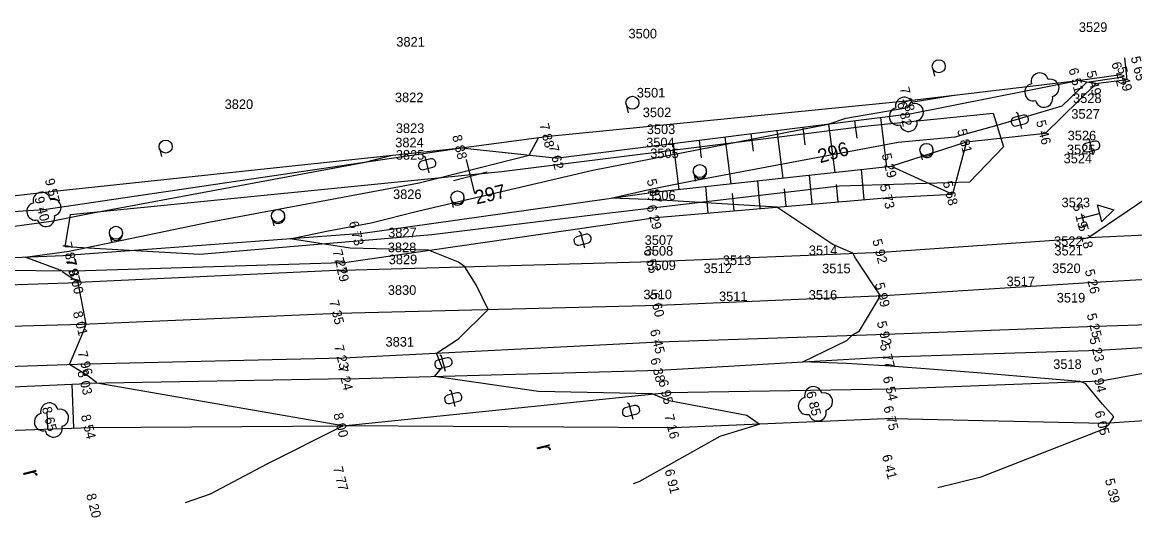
# Model space of a CAD drawing. Extents: x -740053 to -737517, y -1033516 to -1032488.
# Drawn here: x -739198.5 to -739134.6, y -1032582.4 to -1032554 of the extents above; entities that cross this region are included whole.
import ezdxf

# ---------------------------------------------------------------- set-up
doc = ezdxf.new("R2010")
doc.units = 0
for name, color, linetype in [('bod-cislo', 7, 'Continuous'), ('bod-oznac', 7, 'Continuous'), ('bod-vyska', 7, 'Continuous'), ('bod-vyska100', 7, 'Continuous'), ('Contours', 7, 'Continuous'), ('Contours text', 7, 'Continuous'), ('ctv-sit', 7, 'Continuous'), ('dopr-zariz', 7, 'Continuous'), ('Hranice-zelene', 7, 'Continuous'), ('opěrná zeď', 7, 'Continuous'), ('osa-komunikace', 7, 'Continuous'), ('ploty', 7, 'Continuous'), ('Rozhrani-ploch', 7, 'Continuous'), ('silnice', 7, 'Continuous'), ('Technické šrafy', 7, 'Continuous'), ('Terenni-hrana', 7, 'Continuous'), ('Znacky-kultury', 7, 'Continuous')]:
    doc.layers.add(name, color=color, linetype=linetype)

# ---------------------------------------------------------------- blocks, each defined once
blk = doc.blocks.new('POINT_DISPLAY')
blk.add_line((0, 0), (0, 0))
blk = doc.blocks.new('p_strom')
for centre, start, end in [((0, 1), 0, 180), ((-1, 0), 90, 270), ((1, 0), 270, 90), ((0, -1), 180, 0)]:
    blk.add_arc(centre, 1, start, end)
at = {"rotation": -180}
blk.add_blockref('POINT_DISPLAY', (0, 0), dxfattribs=at)
blk = doc.blocks.new('d_znacka')
for p, q in [((-1, 2), (0, 3.73)), ((0, 3.73), (1, 2)), ((-1, 2), (1, 2)), ((0, 0), (0, 2)), ((-0.5, 0), (0.5, 0))]:
    blk.add_line(p, q)
blk = doc.blocks.new('p_orna')
blk.add_text('r', height=2).set_placement((0, 0))
blk = doc.blocks.new('p_zahr')
blk.add_line((0, -0.75), (0.99, -0.75))
blk.add_circle((0, 0), 0.75)
blk = doc.blocks.new('p_leskro')
blk.add_line((0, -0.75), (1, -0.75))
blk.add_circle((0, 0), 0.75)
blk.add_arc((0.13, 0), 0.75, 264.8832, 95.1168)
blk = doc.blocks.new('p_neplod')
for p, q in [((-0.82, 0), (-0.99, -0.18)), ((1, 0), (-0.82, 0)), ((-0.49, 0.56), (-0.49, -0.55)), ((0.05, 1.01), (-0.04, 1.01)), ((0.5, -0.55), (0.5, 0.56)), ((-0.04, -1), (0.05, -1))]:
    blk.add_line(p, q)
for centre, start, end in [((-0.04, 0.56), 90, 180), ((0.05, 0.56), 0, 90), ((-0.04, -0.55), 180, 270), ((0.05, -0.55), 270, 0)]:
    blk.add_arc(centre, 0.45, start, end)
blk = doc.blocks.new('ctvsit')
for p, q in [((0, -2), (0, 2)), ((2, 0), (-2, 0))]:
    blk.add_line(p, q)

msp = doc.modelspace()

# ---------------------------------------------------------------- linework, layer by layer
at = {"layer": 'Contours'}
for points in [[(-739145.903, -1032580.714), (-739143.412, -1032580.105), (-739136.31, -1032577.325), (-739136.077, -1032577.088), (-739136.023, -1032577.005), (-739135.783, -1032576.653), (-739136.438, -1032575.919), (-739137.422, -1032574.749), (-739137.735, -1032574.634), (-739143.625, -1032574.134), (-739148.633, -1032573.753), (-739151.163, -1032573.601), (-739153.655, -1032573.497), (-739151.118, -1032572.266), (-739150.822, -1032571.972), (-739150.391, -1032571.71), (-739149.18, -1032569.704), (-739150.618, -1032567.555), (-739150.782, -1032567.263), (-739151.916, -1032566.766), (-739155.143, -1032564.612), (-739162.071, -1032564.197), (-739164.654, -1032564.106), (-739162.485, -1032563.599), (-739160.101, -1032563.134), (-739148.17, -1032560.89), (-739144.889, -1032560.576), (-739142.492, -1032559.91), (-739138.749, -1032558.809), (-739137.338, -1032557.441), (-739136.037, -1032557.244), (-739135.233, -1032557.138)], [(-739163.362, -1032580.476), (-739163.036, -1032580.363), (-739161.046, -1032579.267), (-739158.384, -1032577.774), (-739156.144, -1032577.082), (-739156.853, -1032576.579), (-739161.322, -1032575.737), (-739162.296, -1032575.342), (-739168.833, -1032575.205), (-739174.799, -1032574.34), (-739174.361, -1032573.831), (-739174.676, -1032573.002), (-739173.412, -1032572.172), (-739171.72, -1032570.488), (-739172.411, -1032569.087), (-739173.061, -1032568.042), (-739173.41, -1032567.779), (-739175.135, -1032567.093), (-739179.639, -1032566.976), (-739183.077, -1032566.433), (-739181.004, -1032566.002), (-739178.433, -1032565.524), (-739175.693, -1032564.828), (-739165.698, -1032562.493), (-739152.197, -1032559.857), (-739151.186, -1032559.505), (-739147.612, -1032558.898), (-739147.431, -1032558.594), (-739144.948, -1032558.197)], [(-739189.105, -1032581.577), (-739187.658, -1032581.076), (-739184.4, -1032579.357), (-739180.063, -1032577.173), (-739194.194, -1032574.728), (-739194.209, -1032574.683), (-739194.755, -1032574.258), (-739195.759, -1032573.652), (-739194.965, -1032571.794), (-739194.797, -1032571.328), (-739195.262, -1032568.944), (-739196.14, -1032568.348), (-739196.148, -1032568.294), (-739198.308, -1032567.486), (-739195.773, -1032567.145), (-739187.763, -1032565.479), (-739175.672, -1032563.232), (-739169.364, -1032561.628), (-739168.834, -1032560.631)], [(-739207.093, -1032566.812), (-739196.811, -1032565.432), (-739194.522, -1032564.956), (-739178.777, -1032562.03), (-739177.31, -1032561.649)]]:
    msp.add_lwpolyline(points, dxfattribs=at)
at = {"layer": 'Hranice-zelene'}
msp.add_lwpolyline([(-739142.712, -1032559.222), (-739142.121, -1032561.159), (-739144.075, -1032563.185), (-739151.537, -1032563.412), (-739165.544, -1032565.062), (-739174.944, -1032566.211), (-739188.273, -1032567.342), (-739196, -1032566.905), (-739195.699, -1032565.04), (-739170.946, -1032562.575), (-739150.099, -1032559.967), (-739142.712, -1032559.222)], dxfattribs=at)
at = {"layer": 'opěrná zeď'}
msp.add_lwpolyline([(-739135.171, -1032556.046), (-739135.048, -1032557.301), (-739136.821, -1032557.535)], dxfattribs=at)
at = {"layer": 'osa-komunikace'}
for p, q in [((-739136.91, -1032568.928), (-739121.644, -1032568.086)), ((-739148.968, -1032569.695), (-739136.91, -1032568.928)), ((-739161.913, -1032570.252), (-739148.968, -1032569.695)), ((-739195.02, -1032571.338), (-739180.302, -1032570.695)), ((-739180.302, -1032570.695), (-739161.913, -1032570.252)), ((-739213.808, -1032571.829), (-739195.02, -1032571.338))]:
    msp.add_line(p, q, dxfattribs=at)
at = {"layer": 'ploty'}
for p, q in [((-739147.526, -1032558.505), (-739137.85, -1032557.349)), ((-739137.85, -1032557.349), (-739135.386, -1032557.002)), ((-739168.233, -1032560.552), (-739147.526, -1032558.505)), ((-739173.242, -1032561.215), (-739168.233, -1032560.552)), ((-739196.631, -1032563.71), (-739173.242, -1032561.215)), ((-739206.001, -1032564.749), (-739196.631, -1032563.71))]:
    msp.add_line(p, q, dxfattribs=at)
at = {"layer": 'Rozhrani-ploch'}
msp.add_line((-739137.285, -1032566.373), (-739133.891, -1032564.085), dxfattribs=at)
at = {"layer": 'silnice'}
for p, q in [((-739121.378, -1032565.699), (-739137.285, -1032566.373)), ((-739149.112, -1032567.195), (-739137.285, -1032566.373)), ((-739162.259, -1032567.731), (-739149.112, -1032567.195)), ((-739180.022, -1032568.242), (-739195.262, -1032568.944)), ((-739180.022, -1032568.242), (-739162.259, -1032567.731)), ((-739213.756, -1032569.578), (-739195.262, -1032568.944)), ((-739148.855, -1032571.905), (-739136.799, -1032571.458)), ((-739136.799, -1032571.458), (-739121.661, -1032570.926)), ((-739161.89, -1032572.35), (-739148.855, -1032571.905)), ((-739180.023, -1032573.275), (-739161.89, -1032572.35)), ((-739194.745, -1032573.619), (-739180.023, -1032573.275)), ((-739213.761, -1032574.23), (-739194.745, -1032573.619))]:
    msp.add_line(p, q, dxfattribs=at)
at = {"layer": 'Technické šrafy'}
for p, q in [((-739152.164, -1032559.853), (-739151.815, -1032562.628)), ((-739150.676, -1032559.665), (-739150.551, -1032560.658)), ((-739149.187, -1032559.478), (-739148.832, -1032562.303)), ((-739158.117, -1032560.602), (-739157.78, -1032563.277)), ((-739156.629, -1032560.415), (-739156.504, -1032561.407)), ((-739155.14, -1032560.227), (-739154.797, -1032562.952)), ((-739153.652, -1032560.04), (-739153.527, -1032561.032)), ((-739161.093, -1032560.977), (-739160.763, -1032563.601)), ((-739159.605, -1032560.789), (-739159.48, -1032561.782)), ((-739150.123, -1032564.18), (-739150.272, -1032562.46)), ((-739156.101, -1032564.695), (-739156.238, -1032563.109)), ((-739153.112, -1032564.437), (-739153.255, -1032562.784)), ((-739159.09, -1032564.953), (-739159.221, -1032563.433)), ((-739157.596, -1032564.824), (-739157.682, -1032563.828)), ((-739154.607, -1032564.566), (-739154.693, -1032563.57)), ((-739151.618, -1032564.309), (-739151.704, -1032563.312)), ((-739195.503, -1032577.299), (-739195.596, -1032574.774)), ((-739197.002, -1032577.355), (-739197.039, -1032576.356))]:
    msp.add_line(p, q, dxfattribs=at)
at = {"layer": 'Terenni-hrana'}
for p, q in [((-739147.699, -1032559.291), (-739137.85, -1032557.349)), ((-739136.821, -1032557.535), (-739137.85, -1032557.349)), ((-739139.711, -1032560.37), (-739136.821, -1032557.535)), ((-739147.699, -1032559.291), (-739167.69, -1032561.807)), ((-739144.238, -1032560.874), (-739139.711, -1032560.37)), ((-739197.226, -1032564.747), (-739173.242, -1032561.215)), ((-739173.242, -1032561.215), (-739167.69, -1032561.807)), ((-739148.577, -1032562.275), (-739144.238, -1032560.874)), ((-739144.238, -1032560.874), (-739145.06, -1032563.875)), ((-739162.067, -1032563.743), (-739148.577, -1032562.275)), ((-739148.577, -1032562.275), (-739145.06, -1032563.875)), ((-739179.179, -1032566.143), (-739162.067, -1032563.743)), ((-739162.079, -1032565.21), (-739148.686, -1032564.056)), ((-739148.686, -1032564.056), (-739145.06, -1032563.875)), ((-739213.294, -1032565.843), (-739197.226, -1032564.747)), ((-739180.1, -1032567.808), (-739162.079, -1032565.21)), ((-739179.179, -1032566.143), (-739195.638, -1032567.368)), ((-739213.506, -1032568.154), (-739195.638, -1032567.368)), ((-739195.445, -1032568.299), (-739213.506, -1032568.154)), ((-739180.1, -1032567.808), (-739195.445, -1032568.299)), ((-739136.649, -1032572.833), (-739121.698, -1032571.925)), ((-739136.537, -1032574.589), (-739121.698, -1032571.925)), ((-739161.871, -1032573.985), (-739148.683, -1032573.202)), ((-739148.683, -1032573.202), (-739136.649, -1032572.833)), ((-739179.803, -1032574.478), (-739161.871, -1032573.985)), ((-739179.803, -1032574.478), (-739194.762, -1032574.737)), ((-739148.517, -1032575.047), (-739136.537, -1032574.589)), ((-739213.662, -1032575.566), (-739194.762, -1032574.737)), ((-739180.063, -1032577.173), (-739161.408, -1032575.25)), ((-739161.408, -1032575.25), (-739148.517, -1032575.047)), ((-739136.356, -1032577.028), (-739122.848, -1032576.082)), ((-739194.559, -1032577.264), (-739180.063, -1032577.173)), ((-739161.048, -1032577.294), (-739180.063, -1032577.173)), ((-739148.481, -1032576.75), (-739161.048, -1032577.294)), ((-739148.481, -1032576.75), (-739136.356, -1032577.028)), ((-739213.49, -1032577.967), (-739194.559, -1032577.264))]:
    msp.add_line(p, q, dxfattribs=at)

# ---------------------------------------------------------------- block references
at = {"layer": 'bod-oznac', "rotation": -75.86979040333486}
for p in [(-739137.85, -1032557.349), (-739135.386, -1032557.003), (-739135.048, -1032557.301), (-739136.821, -1032557.535), (-739147.526, -1032558.505), (-739147.699, -1032559.291), (-739168.233, -1032560.552), (-739139.711, -1032560.37), (-739173.242, -1032561.215), (-739144.238, -1032560.874), (-739167.69, -1032561.807), (-739148.577, -1032562.275), (-739196.631, -1032563.71), (-739162.067, -1032563.743), (-739148.686, -1032564.056), (-739145.06, -1032563.875), (-739197.226, -1032564.747), (-739162.079, -1032565.21), (-739137.595, -1032565.224), (-739179.179, -1032566.143), (-739137.285, -1032566.373), (-739195.638, -1032567.368), (-739149.112, -1032567.195), (-739195.445, -1032568.299), (-739180.1, -1032567.808), (-739180.022, -1032568.242), (-739162.259, -1032567.731), (-739195.262, -1032568.944), (-739136.91, -1032568.928), (-739148.968, -1032569.695), (-739180.302, -1032570.695), (-739161.913, -1032570.252), (-739195.02, -1032571.338), (-739136.799, -1032571.458), (-739148.855, -1032571.905), (-739161.89, -1032572.35), (-739180.023, -1032573.275), (-739148.683, -1032573.202), (-739136.649, -1032572.833), (-739194.745, -1032573.619), (-739161.871, -1032573.985), (-739179.803, -1032574.478), (-739136.537, -1032574.589), (-739194.762, -1032574.737), (-739161.408, -1032575.25), (-739148.517, -1032575.047), (-739152.92, -1032575.908), (-739196.791, -1032576.836), (-739180.063, -1032577.173), (-739148.481, -1032576.75), (-739136.356, -1032577.028), (-739194.559, -1032577.264), (-739161.048, -1032577.294), (-739148.561, -1032579.544), (-739180.072, -1032580.248), (-739161.045, -1032580.377), (-739135.753, -1032580.939), (-739194.253, -1032581.797)]:
    msp.add_blockref('POINT_DISPLAY', p, dxfattribs=at)
at = {"layer": 'ctv-sit', "xscale": 0.49999999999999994, "yscale": 0.5, "rotation": 104.13020959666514}
msp.add_blockref('ctvsit', (-739172.735, -1032562.861), dxfattribs=at)
at = {"layer": 'dopr-zariz', "xscale": 0.49999999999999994, "yscale": 0.4999999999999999, "rotation": -75.86979040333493}
msp.add_blockref('d_znacka', (-739137.595, -1032565.224), dxfattribs=at)
at = {"layer": 'Znacky-kultury', "xscale": 0.49999999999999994}
for name, p, yscale, rotation in [('p_zahr', (-739145.841, -1032556.531), 0.5, -75.86979040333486), ('p_strom', (-739139.917, -1032557.898), 0.5, -75.86979040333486), ('p_strom', (-739147.699, -1032559.291), 0.4999999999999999, -75.86979040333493), ('p_zahr', (-739163.434, -1032558.627), 0.5, -75.86979040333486), ('p_neplod', (-739141.192, -1032559.647), 0.5, -75.86979040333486), ('p_neplod', (-739137.089, -1032561.132), 0.5, -75.86979040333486), ('p_zahr', (-739190.234, -1032561.141), 0.5, -75.86979040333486), ('p_leskro', (-739146.547, -1032561.335), 0.5, -75.86979040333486), ('p_neplod', (-739175.218, -1032562.157), 0.5, -75.86979040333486), ('p_leskro', (-739159.562, -1032562.546), 0.5, -75.86979040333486), ('p_strom', (-739197.226, -1032564.747), 0.4999999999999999, -75.86979040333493), ('p_leskro', (-739173.481, -1032564.062), 0.5, -75.86979040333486), ('p_leskro', (-739183.783, -1032565.121), 0.5, -75.86979040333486), ('p_leskro', (-739193.089, -1032566.091), 0.5, -75.86979040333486), ('p_neplod', (-739166.295, -1032566.484), 0.5, -75.86979040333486), ('p_neplod', (-739174.287, -1032573.574), 0.5, -75.86979040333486), ('p_strom', (-739152.92, -1032575.908), 0.4999999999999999, -75.86979040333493), ('p_neplod', (-739173.723, -1032575.582), 0.5, -75.86979040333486), ('p_strom', (-739196.791, -1032576.836), 0.4999999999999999, -75.86979040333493), ('p_neplod', (-739163.515, -1032576.317), 0.5, -75.86979040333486), ('p_orna', (-739168.961, -1032578.328), 0.5, -75.86979040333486), ('p_orna', (-739198.443, -1032579.795), 0.5, -75.86979040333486)]:
    msp.add_blockref(name, p, dxfattribs=dict(at, yscale=yscale, rotation=rotation))

# ---------------------------------------------------------------- texts
at = {"layer": 'bod-cislo'}
for s, p in [('3529', (-739137.795, -1032554.563)), ('3821', (-739176.989, -1032555.403)), ('3500', (-739163.658, -1032554.933)), ('3822', (-739177.068, -1032558.593)), ('3501', (-739163.179, -1032558.323)), ('3528', (-739138.128, -1032558.643)), ('3820', (-739186.848, -1032558.983)), ('3502', (-739162.838, -1032559.453)), ('3527', (-739138.228, -1032559.543)), ('3823', (-739177.018, -1032560.363)), ('3503', (-739162.608, -1032560.423)), ('3824', (-739177.051, -1032561.183)), ('3504', (-739162.641, -1032561.183)), ('3526', (-739138.438, -1032560.783)), ('3505', (-739162.408, -1032561.803)), ('3525', (-739138.478, -1032561.583)), ('3825', (-739177.018, -1032561.893)), ('3524', (-739138.671, -1032562.103)), ('3826', (-739177.178, -1032564.153)), ('3506', (-739162.588, -1032564.213)), ('3523', (-739138.788, -1032564.623)), ('3827', (-739177.458, -1032566.353)), ('3507', (-739162.728, -1032566.783)), ('3522', (-739139.218, -1032566.843)), ('3828', (-739177.478, -1032567.203)), ('3508', (-739162.728, -1032567.403)), ('3514', (-739153.301, -1032567.373)), ('3521', (-739139.199, -1032567.393)), ('3829', (-739177.425, -1032567.893)), ('3513', (-739158.238, -1032567.943)), ('3509', (-739162.575, -1032568.233)), ('3512', (-739159.348, -1032568.403)), ('3515', (-739152.538, -1032568.413)), ('3520', (-739139.328, -1032568.403)), ('3517', (-739141.948, -1032569.153)), ('3830', (-739177.478, -1032569.653)), ('3510', (-739162.798, -1032569.903)), ('3511', (-739158.459, -1032570.013)), ('3516', (-739153.308, -1032569.933)), ('3519', (-739139.065, -1032570.093)), ('3831', (-739177.609, -1032572.623)), ('3518', (-739139.268, -1032573.903))]:
    msp.add_text(s, height=0.55, dxfattribs=at).set_placement(p)
at = {"layer": 'bod-vyska'}
for s, p in [('5 65', (-739134.822, -1032556.029)), ('6 51', (-739138.392, -1032556.698)), ('5 49', (-739137.369, -1032556.859)), ('6 42', (-739135.928, -1032556.352)), ('5 49', (-739135.596, -1032556.626)), ('7 18', (-739148.084, -1032557.791)), ('6 82', (-739148.241, -1032558.641)), ('7 88', (-739168.781, -1032559.876)), ('5 46', (-739140.259, -1032559.695)), ('8 88', (-739173.79, -1032560.539)), ('5 81', (-739144.786, -1032560.198)), ('7 62', (-739168.241, -1032561.119)), ('5 29', (-739149.125, -1032561.6)), ('9 57', (-739197.176, -1032563.047)), ('5 87', (-739162.615, -1032563.067)), ('5 68', (-739145.611, -1032563.187)), ('5 73', (-739149.234, -1032563.38)), ('9 40', (-739197.771, -1032564.084)), ('5 19', (-739138.153, -1032564.51)), ('6 29', (-739162.621, -1032564.56)), ('6 73', (-739179.721, -1032565.493)), ('5 18', (-739137.843, -1032565.659)), ('7 87', (-739196.186, -1032566.693)), ('6 55', (-739162.801, -1032567.08)), ('5 92', (-739149.66, -1032566.519)), ('7 97', (-739195.993, -1032567.624)), ('7 27', (-739180.648, -1032567.133)), ('7 29', (-739180.57, -1032567.567)), ('8 00', (-739195.81, -1032568.269)), ('5 26', (-739137.458, -1032568.253)), ('5 99', (-739149.516, -1032569.02)), ('6 60', (-739162.458, -1032569.59)), ('7 35', (-739180.85, -1032570.019)), ('8 01', (-739195.568, -1032570.662)), ('5 25', (-739137.347, -1032570.782)), ('5 92', (-739149.403, -1032571.229)), ('6 45', (-739162.432, -1032571.7)), ('5 23', (-739137.197, -1032572.157)), ('7 23', (-739180.571, -1032572.599)), ('5 77', (-739149.231, -1032572.526)), ('7 96', (-739195.293, -1032572.944)), ('6 38', (-739162.412, -1032573.335)), ('8 03', (-739195.31, -1032574.062)), ('7 24', (-739180.351, -1032573.802)), ('5 94', (-739137.085, -1032573.913)), ('6 95', (-739161.95, -1032574.6)), ('6 54', (-739149.059, -1032574.397)), ('6 85', (-739153.462, -1032575.258)), ('8 65', (-739197.343, -1032576.148)), ('8 54', (-739195.107, -1032576.589)), ('8 00', (-739180.611, -1032576.497)), ('7 16', (-739161.606, -1032576.581)), ('6 75', (-739149.022, -1032576.1)), ('6 05', (-739136.898, -1032576.378)), ('6 41', (-739149.103, -1032578.894)), ('7 77', (-739180.621, -1032579.572)), ('6 91', (-739161.587, -1032579.727)), ('5 39', (-739136.301, -1032580.264)), ('8 20', (-739194.802, -1032581.121))]:
    msp.add_text(s, height=0.55, rotation=284.13021, dxfattribs=at).set_placement(p)
at = {"layer": 'bod-vyska100'}
for s, p in [('296 51', (-739137.923, -1032557.195)), ('295 49', (-739136.894, -1032557.381)), ('296 42', (-739135.459, -1032556.848)), ('295 49', (-739135.121, -1032557.148)), ('297 18', (-739147.6, -1032558.347)), ('296 82', (-739147.772, -1032559.137)), ('297 88', (-739168.306, -1032560.398)), ('295 46', (-739139.784, -1032560.217)), ('298 88', (-739173.315, -1032561.061)), ('295 81', (-739144.311, -1032560.72)), ('297 62', (-739167.763, -1032561.652)), ('295 29', (-739148.65, -1032562.122)), ('299 57', (-739196.704, -1032563.557)), ('295 87', (-739162.14, -1032563.589)), ('295 68', (-739145.133, -1032563.72)), ('295 73', (-739148.759, -1032563.902)), ('299 40', (-739197.299, -1032564.594)), ('296 29', (-739162.152, -1032565.057)), ('295 19', (-739137.669, -1032565.066)), ('296 73', (-739179.252, -1032565.989)), ('295 18', (-739137.359, -1032566.215)), ('297 87', (-739195.711, -1032567.214)), ('297 27', (-739180.173, -1032567.655)), ('296 55', (-739162.332, -1032567.577)), ('295 92', (-739149.185, -1032567.041)), ('297 97', (-739195.518, -1032568.145)), ('297 29', (-739180.095, -1032568.089)), ('298 00', (-739195.335, -1032568.79)), ('295 26', (-739136.983, -1032568.775)), ('295 99', (-739149.041, -1032569.541)), ('296 60', (-739161.987, -1032570.098)), ('297 35', (-739180.375, -1032570.541)), ('298 01', (-739195.093, -1032571.184)), ('295 25', (-739136.872, -1032571.304)), ('295 92', (-739148.928, -1032571.751)), ('296 45', (-739161.963, -1032572.197)), ('295 23', (-739136.722, -1032572.679)), ('297 23', (-739180.096, -1032573.121)), ('295 77', (-739148.756, -1032573.048)), ('297 96', (-739194.818, -1032573.466)), ('296 38', (-739161.944, -1032573.831)), ('298 03', (-739194.835, -1032574.584)), ('297 24', (-739179.876, -1032574.324)), ('295 94', (-739136.61, -1032574.435)), ('296 95', (-739161.481, -1032575.097)), ('296 54', (-739148.59, -1032574.893)), ('296 85', (-739152.993, -1032575.754)), ('296 75', (-739148.554, -1032576.596)), ('298 65', (-739196.865, -1032576.681)), ('298 54', (-739194.632, -1032577.111)), ('298 00', (-739180.136, -1032577.019)), ('297 16', (-739161.122, -1032577.137)), ('296 05', (-739136.429, -1032576.874)), ('296 41', (-739148.634, -1032579.39)), ('297 77', (-739180.146, -1032580.094)), ('296 91', (-739161.118, -1032580.223)), ('295 39', (-739135.826, -1032580.786)), ('298 20', (-739194.326, -1032581.643))]:
    msp.add_text(s, height=0.05, rotation=284.13021, dxfattribs=at).set_placement(p)
at = {"layer": 'Contours text'}
for s, rotation, p in [('296', 16.39637, (-739152.651, -1032562.106)), ('297', 13.14694, (-739172.385, -1032564.466))]:
    msp.add_text(s, height=0.8, rotation=rotation, dxfattribs=at).set_placement(p)

doc.saveas('drawing.dxf')
